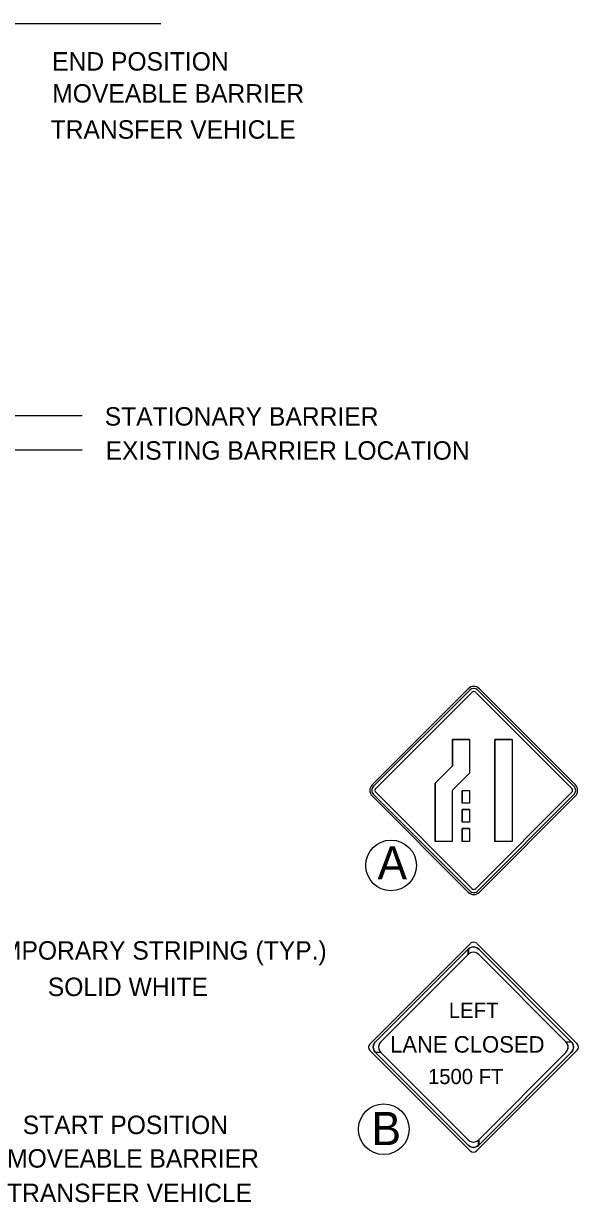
# Model space of a CAD drawing. Extents: x 1531.4 to 1538.6, y 1529.6 to 1539.6.
# Drawn here: x 1536.256 to 1538.064, y 1533.747 to 1537.583 of the extents above; entities that cross this region are included whole.
import ezdxf

# ---------------------------------------------------------------- set-up
doc = ezdxf.new("R2010")
doc.units = 0
for name, color, linetype in [('DETL-DIMS', 7, 'Continuous'), ('DETL-LINE', 7, 'Continuous'), ('DETL-NOTE', 7, 'Continuous')]:
    doc.layers.add(name, color=color, linetype=linetype)

msp = doc.modelspace()

# ---------------------------------------------------------------- linework, layer by layer
at = {"layer": 'DETL-DIMS'}
for p, q in [((1535.9269, 1536.3072), (1536.4477, 1536.3072)), ((1535.7051, 1536.1962), (1536.4477, 1536.1962))]:
    msp.add_line(p, q, dxfattribs=at)
at = {"layer": 'DETL-LINE'}
for p, q in [((1536.1749, 1537.5829), (1536.7036, 1537.5829)), ((1537.705, 1535.4187), (1537.3917, 1535.106)), ((1537.7096, 1535.4141), (1537.3963, 1535.1014)), ((1538.0493, 1535.1014), (1537.7366, 1535.4141)), ((1538.0539, 1535.106), (1537.7412, 1535.4187)), ((1537.7169, 1535.4069), (1537.4035, 1535.0942)), ((1538.0421, 1535.0942), (1537.7294, 1535.4069)), ((1537.7095, 1535.2539), (1537.6537, 1535.2539)), ((1537.6537, 1535.2539), (1537.6537, 1535.1674)), ((1537.6537, 1535.1674), (1537.6537, 1535.2539)), ((1537.6537, 1535.2539), (1537.7095, 1535.2539)), ((1537.7095, 1535.2539), (1537.7095, 1535.1443)), ((1537.7095, 1535.2539), (1537.7095, 1535.1443)), ((1537.7918, 1535.2539), (1537.7918, 1534.922)), ((1537.8476, 1535.2539), (1537.7918, 1535.2539)), ((1537.7918, 1534.922), (1537.7918, 1535.2539)), ((1537.7918, 1535.2539), (1537.8476, 1535.2539)), ((1537.8476, 1535.2539), (1537.8476, 1534.922)), ((1537.8476, 1535.2539), (1537.8476, 1534.922)), ((1537.5973, 1535.111), (1537.6537, 1535.1674)), ((1537.5973, 1535.111), (1537.6537, 1535.1674)), ((1537.6531, 1535.0879), (1537.7095, 1535.1443)), ((1537.7095, 1535.1443), (1537.6531, 1535.0879)), ((1537.5973, 1535.111), (1537.5973, 1534.922)), ((1537.5973, 1534.922), (1537.5973, 1535.111)), ((1537.3917, 1535.0698), (1537.705, 1534.7565)), ((1537.3963, 1535.0744), (1537.7096, 1534.7611)), ((1537.4035, 1535.0817), (1537.7169, 1534.7683)), ((1537.6531, 1535.0879), (1537.6531, 1534.922)), ((1537.6531, 1535.0879), (1537.6531, 1534.922)), ((1537.6848, 1535.0879), (1537.6848, 1535.0465)), ((1537.6848, 1535.0465), (1537.6848, 1535.0879)), ((1537.6848, 1535.0879), (1537.7095, 1535.0879)), ((1537.7095, 1535.0879), (1537.7095, 1535.0465)), ((1537.7095, 1535.0879), (1537.7095, 1535.0465)), ((1537.7294, 1534.7683), (1538.0421, 1535.0817)), ((1537.7366, 1534.7611), (1538.0493, 1535.0744)), ((1537.7412, 1534.7565), (1538.0539, 1535.0698)), ((1537.7095, 1535.0465), (1537.6848, 1535.0465)), ((1537.7095, 1535.0465), (1537.6848, 1535.0465)), ((1537.7095, 1535.0257), (1537.6848, 1535.0257)), ((1537.6848, 1535.0257), (1537.6848, 1534.9842)), ((1537.6848, 1534.9842), (1537.6848, 1535.0257)), ((1537.6848, 1535.0257), (1537.7095, 1535.0257)), ((1537.7095, 1535.0257), (1537.7095, 1534.9842)), ((1537.7095, 1535.0257), (1537.7095, 1534.9842)), ((1537.7095, 1534.9842), (1537.6848, 1534.9842)), ((1537.7095, 1534.9842), (1537.6848, 1534.9842)), ((1537.7095, 1534.9635), (1537.6848, 1534.9635)), ((1537.6848, 1534.9635), (1537.6848, 1534.922)), ((1537.6848, 1534.922), (1537.6848, 1534.9635)), ((1537.6848, 1534.9635), (1537.7095, 1534.9635)), ((1537.7095, 1534.9635), (1537.7095, 1534.922)), ((1537.7095, 1534.9635), (1537.7095, 1534.922)), ((1537.6531, 1534.922), (1537.5973, 1534.922)), ((1537.6531, 1534.922), (1537.5973, 1534.922)), ((1537.7095, 1534.922), (1537.6848, 1534.922)), ((1537.7095, 1534.922), (1537.6848, 1534.922)), ((1537.8476, 1534.922), (1537.7918, 1534.922)), ((1537.8476, 1534.922), (1537.7918, 1534.922)), ((1537.7122, 1534.5902), (1537.3842, 1534.2622)), ((1537.4026, 1534.2699), (1537.7042, 1534.5715)), ((1538.0598, 1534.263), (1537.7325, 1534.5902)), ((1537.739, 1534.5715), (1538.0406, 1534.2699)), ((1537.7042, 1534.5541), (1537.42, 1534.2699)), ((1538.0232, 1534.2699), (1537.739, 1534.5541)), ((1537.3842, 1534.2419), (1537.7114, 1533.9147)), ((1537.7042, 1533.9335), (1537.4026, 1534.2351)), ((1537.42, 1534.2351), (1537.7042, 1533.9509)), ((1537.7318, 1533.9147), (1538.0598, 1534.2427)), ((1538.0406, 1534.2351), (1537.739, 1533.9335)), ((1537.739, 1533.9509), (1538.0232, 1534.2351))]:
    msp.add_line(p, q, dxfattribs=at)
for points in [[(1537.4026, 1534.2699), (1537.6955, 1534.5628), (1537.7053, 1534.5725), (1537.7042, 1534.5541), (1537.42, 1534.2699), (1537.4155, 1534.2638), (1537.4129, 1534.2547), (1537.4136, 1534.2464), (1537.4158, 1534.2406), (1537.42, 1534.2351), (1537.4026, 1534.2351), (1537.3977, 1534.2422), (1537.3954, 1534.2516), (1537.3962, 1534.2586), (1537.3984, 1534.2642)], [(1537.739, 1534.5714), (1538.0318, 1534.2786), (1538.0416, 1534.2688), (1538.0232, 1534.2699), (1537.739, 1534.5541), (1537.7328, 1534.5586), (1537.7238, 1534.5612), (1537.7154, 1534.5605), (1537.7097, 1534.5582), (1537.7042, 1534.5541), (1537.7042, 1534.5714), (1537.7112, 1534.5764), (1537.7207, 1534.5787), (1537.7276, 1534.5779), (1537.7333, 1534.5757)], [(1538.0405, 1534.2351), (1537.7476, 1533.9422), (1537.7379, 1533.9325), (1537.739, 1533.9509), (1538.0232, 1534.2351), (1538.0277, 1534.2412), (1538.0303, 1534.2503), (1538.0296, 1534.2587), (1538.0273, 1534.2644), (1538.0232, 1534.2699), (1538.0405, 1534.2699), (1538.0455, 1534.2628), (1538.0478, 1534.2534), (1538.047, 1534.2465), (1538.0448, 1534.2408)], [(1537.7042, 1533.9336), (1537.4113, 1534.2264), (1537.4016, 1534.2362), (1537.42, 1534.2351), (1537.7042, 1533.9509), (1537.7103, 1533.9464), (1537.7194, 1533.9438), (1537.7278, 1533.9445), (1537.7335, 1533.9468), (1537.739, 1533.9509), (1537.739, 1533.9336), (1537.7319, 1533.9286), (1537.7225, 1533.9263), (1537.7156, 1533.9271), (1537.7098, 1533.9293)]]:
    msp.add_lwpolyline(points, close=True, dxfattribs=at)
for centre in [(1537.4536, 1534.8437), (1537.4296, 1533.9855)]:
    msp.add_circle(centre, 0.0824, dxfattribs=at)
for centre, radius, start, end in [((1537.7231, 1535.4005), 0.0257, 45, 134.94), ((1537.7231, 1535.4009), 0.0189, 45, 134.94), ((1537.7231, 1535.401), 0.00857, 45, 134.94), ((1537.4099, 1535.0879), 0.0257, 134.9399, 225), ((1538.0357, 1535.0879), 0.0257, 315.0601, 45), ((1537.4095, 1535.0879), 0.0189, 134.9399, 225), ((1537.4094, 1535.0879), 0.00857, 134.9399, 225), ((1538.0362, 1535.0879), 0.00857, 315.0601, 45), ((1538.0361, 1535.0879), 0.0189, 315.0601, 45), ((1537.7231, 1534.7743), 0.0189, 225, 315.06), ((1537.7231, 1534.7742), 0.00857, 225, 315.06), ((1537.7231, 1534.7747), 0.0257, 225, 315.06), ((1537.7216, 1534.5541), 0.0246, 45, 135), ((1537.7223, 1534.5801), 0.0144, 45, 135), ((1537.7216, 1534.5367), 0.0246, 45, 135), ((1537.3943, 1534.2521), 0.0144, 135, 225), ((1537.42, 1534.2525), 0.0246, 135, 225), ((1537.4374, 1534.2525), 0.0246, 135, 225), ((1538.0058, 1534.2525), 0.0246, 315, 45), ((1538.0232, 1534.2525), 0.0246, 315, 45), ((1538.0496, 1534.2528), 0.0144, 315, 45), ((1537.7216, 1533.9683), 0.0246, 225, 315), ((1537.7216, 1533.9509), 0.0246, 225, 315), ((1537.7216, 1533.9248), 0.0144, 225, 315)]:
    msp.add_arc(centre, radius, start, end, dxfattribs=at)

# ---------------------------------------------------------------- texts
for s, height, p in [('A', 0.1082, (1537.4094, 1534.798)), ('LEFT', 0.0494, (1537.6419, 1534.3474)), ('LANE CLOSED', 0.053751, (1537.4502, 1534.2346)), ('1500 FT', 0.04932, (1537.5738, 1534.1324)), ('B', 0.1082, (1537.3896, 1533.9336))]:
    msp.add_text(s, height=height, dxfattribs=at).set_placement(p)
at = {"layer": 'DETL-NOTE'}
for s, p in [('END POSITION', (1536.3495, 1537.4299)), ('MOVEABLE BARRIER', (1536.3499, 1537.3258)), ('TRANSFER VEHICLE', (1536.3447, 1537.2083)), ('STATIONARY BARRIER', (1536.5209, 1536.2748)), ('EXISTING BARRIER LOCATION', (1536.5235, 1536.1639)), ('TEMPORARY STRIPING (TYP.)', (1536.0803, 1534.5372)), ('SOLID WHITE', (1536.3354, 1534.4188)), ('START POSITION', (1536.2537, 1533.9696)), ('MOVEABLE BARRIER', (1536.2027, 1533.8605)), ('TRANSFER VEHICLE', (1536.2027, 1533.7481))]:
    msp.add_text(s, height=0.06, dxfattribs=at).set_placement(p)

doc.saveas('drawing.dxf')
